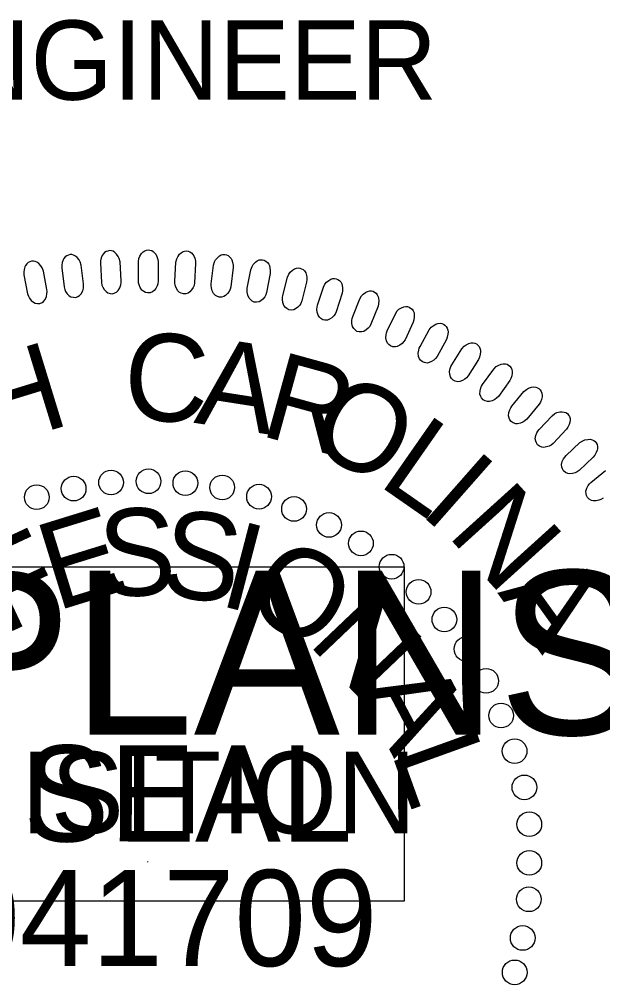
# Model space of a CAD drawing. Extents: x 18938 to 19565, y 6931 to 7973.
# Drawn here: x 19372.4 to 19377.32, y 7796.8 to 7804.94 of the extents above; entities that cross this region are included whole.
import ezdxf

# ---------------------------------------------------------------- set-up
doc = ezdxf.new("R2010")
doc.units = 0
for name, color, linetype in [('Old_Level_10', 7, 'Continuous'), ('Prop Pavement Schedule Description CELL', 7, 'Continuous'), ('Scratch_Level_5', 7, 'Continuous'), ('Typical Pavement Slope Information CELL', 7, 'Continuous')]:
    doc.layers.add(name, color=color, linetype=linetype)

# ---------------------------------------------------------------- blocks, each defined once
blk = doc.blocks.new('Gregory K. Goins')
at = {"layer": 'Old_Level_10'}
blk.add_line((-51.239, 50.97), (-51.239, 50.923), dxfattribs=at)
for points in [[(-55.384, 88.444), (-55.538, 89.661), (-55.602, 89.875), (-55.672, 90.006), (-55.804, 90.161), (-55.914, 90.257), (-56.035, 90.322), (-56.145, 90.349), (-56.258, 90.355), (-56.367, 90.321), (-56.482, 90.276), (-56.578, 90.204), (-56.67, 90.092), (-56.719, 90.005), (-56.767, 89.848), (-56.804, 89.663), (-56.806, 89.502), (-56.656, 88.254), (-56.613, 88.088), (-56.551, 87.955), (-56.442, 87.808), (-56.313, 87.684), (-56.207, 87.617), (-56.044, 87.577), (-55.893, 87.576), (-55.75, 87.634), (-55.652, 87.697), (-55.538, 87.812), (-55.441, 87.995), (-55.397, 88.181), (-55.384, 88.313)], [(-52.946, 88.647), (-53.023, 89.871), (-53.074, 90.088), (-53.135, 90.223), (-53.257, 90.386), (-53.361, 90.49), (-53.478, 90.562), (-53.585, 90.596), (-53.698, 90.608), (-53.809, 90.581), (-53.926, 90.544), (-54.027, 90.478), (-54.125, 90.372), (-54.18, 90.288), (-54.238, 90.135), (-54.286, 89.952), (-54.298, 89.792), (-54.227, 88.537), (-54.195, 88.369), (-54.141, 88.232), (-54.042, 88.079), (-53.921, 87.947), (-53.819, 87.873), (-53.658, 87.823), (-53.508, 87.812), (-53.361, 87.862), (-53.26, 87.918), (-53.139, 88.026), (-53.031, 88.202), (-52.975, 88.386), (-52.953, 88.517)], [(-51.831, 88.656), (-51.831, 89.882), (-51.793, 90.102), (-51.74, 90.242), (-51.628, 90.411), (-51.531, 90.521), (-51.419, 90.601), (-51.315, 90.64), (-51.202, 90.66), (-51.09, 90.64), (-50.97, 90.61), (-50.866, 90.551), (-50.761, 90.451), (-50.701, 90.37), (-50.634, 90.221), (-50.574, 90.042), (-50.552, 89.882), (-50.545, 88.626), (-50.567, 88.456), (-50.613, 88.316), (-50.702, 88.157), (-50.815, 88.017), (-50.912, 87.938), (-51.069, 87.878), (-51.218, 87.858), (-51.367, 87.898), (-51.472, 87.947), (-51.6, 88.047), (-51.719, 88.217), (-51.786, 88.397), (-51.816, 88.526)], [(-49.472, 88.629), (-49.394, 89.854), (-49.344, 90.07), (-49.282, 90.206), (-49.159, 90.368), (-49.056, 90.472), (-48.939, 90.544), (-48.832, 90.577), (-48.718, 90.59), (-48.608, 90.563), (-48.49, 90.526), (-48.39, 90.46), (-48.291, 90.354), (-48.237, 90.27), (-48.179, 90.117), (-48.131, 89.934), (-48.118, 89.773), (-48.191, 88.518), (-48.223, 88.35), (-48.277, 88.214), (-48.377, 88.061), (-48.497, 87.928), (-48.599, 87.854), (-48.76, 87.805), (-48.911, 87.794), (-49.057, 87.843), (-49.158, 87.9), (-49.279, 88.008), (-49.387, 88.184), (-49.443, 88.368), (-49.465, 88.499)], [(-47.109, 88.454), (-46.955, 89.671), (-46.891, 89.884), (-46.821, 90.016), (-46.689, 90.17), (-46.578, 90.267), (-46.457, 90.332), (-46.348, 90.359), (-46.235, 90.364), (-46.126, 90.33), (-46.011, 90.285), (-45.915, 90.213), (-45.823, 90.101), (-45.774, 90.014), (-45.726, 89.857), (-45.69, 89.671), (-45.687, 89.511), (-45.838, 88.263), (-45.881, 88.097), (-45.943, 87.965), (-46.052, 87.818), (-46.181, 87.693), (-46.287, 87.626), (-46.451, 87.587), (-46.601, 87.585), (-46.745, 87.644), (-46.842, 87.706), (-46.956, 87.821), (-47.054, 88.005), (-47.097, 88.191), (-47.111, 88.324)], [(-57.766, 88.076), (-57.995, 89.281), (-58.073, 89.489), (-58.15, 89.617), (-58.292, 89.763), (-58.408, 89.852), (-58.533, 89.91), (-58.643, 89.929), (-58.758, 89.928), (-58.864, 89.887), (-58.975, 89.835), (-59.067, 89.757), (-59.152, 89.639), (-59.195, 89.55), (-59.233, 89.39), (-59.258, 89.203), (-59.251, 89.042), (-59.023, 87.806), (-58.969, 87.644), (-58.899, 87.515), (-58.781, 87.375), (-58.645, 87.259), (-58.534, 87.199), (-58.369, 87.169), (-58.219, 87.178), (-58.079, 87.245), (-57.985, 87.314), (-57.879, 87.435), (-57.794, 87.624), (-57.761, 87.813), (-57.756, 87.946)], [(-44.77, 88.168), (-44.54, 89.372), (-44.462, 89.581), (-44.384, 89.708), (-44.242, 89.854), (-44.126, 89.943), (-44.001, 90), (-43.891, 90.02), (-43.777, 90.019), (-43.671, 89.978), (-43.559, 89.926), (-43.467, 89.848), (-43.383, 89.73), (-43.339, 89.641), (-43.301, 89.481), (-43.276, 89.294), (-43.284, 89.132), (-43.513, 87.897), (-43.567, 87.735), (-43.637, 87.606), (-43.755, 87.466), (-43.891, 87.35), (-44.002, 87.29), (-44.167, 87.26), (-44.318, 87.269), (-44.457, 87.336), (-44.55, 87.405), (-44.656, 87.527), (-44.742, 87.716), (-44.775, 87.904), (-44.779, 88.038)], [(-42.465, 87.694), (-42.159, 88.882), (-42.069, 89.085), (-41.983, 89.208), (-41.832, 89.344), (-41.711, 89.426), (-41.582, 89.475), (-41.471, 89.488), (-41.357, 89.479), (-41.254, 89.432), (-41.145, 89.373), (-41.059, 89.289), (-40.983, 89.167), (-40.945, 89.075), (-40.917, 88.913), (-40.903, 88.724), (-40.921, 88.563), (-41.227, 87.345), (-41.291, 87.187), (-41.37, 87.062), (-41.496, 86.93), (-41.639, 86.823), (-41.753, 86.769), (-41.92, 86.751), (-42.07, 86.769), (-42.204, 86.845), (-42.293, 86.919), (-42.392, 87.047), (-42.466, 87.241), (-42.486, 87.432), (-42.483, 87.564)], [(-40.215, 87.072), (-39.835, 88.239), (-39.732, 88.436), (-39.639, 88.552), (-39.48, 88.679), (-39.353, 88.753), (-39.222, 88.794), (-39.11, 88.8), (-38.997, 88.784), (-38.897, 88.73), (-38.793, 88.664), (-38.711, 88.575), (-38.643, 88.449), (-38.611, 88.354), (-38.593, 88.191), (-38.592, 88.002), (-38.619, 87.843), (-39.001, 86.646), (-39.075, 86.491), (-39.161, 86.372), (-39.295, 86.248), (-39.446, 86.151), (-39.562, 86.105), (-39.73, 86.096), (-39.879, 86.124), (-40.008, 86.208), (-40.092, 86.288), (-40.183, 86.422), (-40.244, 86.62), (-40.252, 86.811), (-40.24, 86.944)], [(-37.931, 86.337), (-37.48, 87.477), (-37.364, 87.667), (-37.264, 87.778), (-37.097, 87.895), (-36.966, 87.961), (-36.833, 87.993), (-36.721, 87.992), (-36.609, 87.97), (-36.513, 87.91), (-36.412, 87.838), (-36.337, 87.743), (-36.276, 87.612), (-36.25, 87.516), (-36.242, 87.352), (-36.253, 87.163), (-36.291, 87.007), (-36.747, 85.835), (-36.831, 85.686), (-36.924, 85.573), (-37.066, 85.458), (-37.221, 85.369), (-37.341, 85.331), (-37.509, 85.333), (-37.656, 85.37), (-37.78, 85.462), (-37.859, 85.547), (-37.94, 85.686), (-37.988, 85.888), (-37.985, 86.08), (-37.965, 86.211)], [(-35.69, 85.403), (-35.167, 86.513), (-35.04, 86.695), (-34.933, 86.799), (-34.76, 86.905), (-34.625, 86.963), (-34.49, 86.987), (-34.378, 86.979), (-34.268, 86.949), (-34.175, 86.883), (-34.079, 86.805), (-34.01, 86.706), (-33.958, 86.571), (-33.938, 86.474), (-33.941, 86.309), (-33.963, 86.122), (-34.011, 85.968), (-34.54, 84.828), (-34.632, 84.684), (-34.733, 84.577), (-34.882, 84.471), (-35.043, 84.392), (-35.165, 84.361), (-35.332, 84.374), (-35.476, 84.42), (-35.593, 84.52), (-35.667, 84.609), (-35.74, 84.754), (-35.775, 84.958), (-35.76, 85.149), (-35.732, 85.279)], [(-33.566, 84.388), (-32.975, 85.462), (-32.836, 85.636), (-32.723, 85.734), (-32.543, 85.828), (-32.405, 85.877), (-32.268, 85.893), (-32.158, 85.878), (-32.05, 85.841), (-31.961, 85.77), (-31.871, 85.686), (-31.808, 85.583), (-31.764, 85.445), (-31.75, 85.346), (-31.763, 85.183), (-31.798, 84.997), (-31.854, 84.846), (-32.454, 83.742), (-32.555, 83.604), (-32.662, 83.503), (-32.817, 83.407), (-32.983, 83.338), (-33.107, 83.315), (-33.273, 83.338), (-33.414, 83.393), (-33.526, 83.5), (-33.593, 83.594), (-33.656, 83.743), (-33.679, 83.949), (-33.652, 84.139), (-33.616, 84.267)], [(-31.508, 83.203), (-30.85, 84.238), (-30.701, 84.403), (-30.582, 84.493), (-30.397, 84.576), (-30.256, 84.617), (-30.118, 84.624), (-30.009, 84.602), (-29.903, 84.558), (-29.819, 84.481), (-29.735, 84.392), (-29.678, 84.285), (-29.643, 84.145), (-29.636, 84.046), (-29.659, 83.883), (-29.705, 83.699), (-29.771, 83.553), (-30.439, 82.488), (-30.549, 82.357), (-30.661, 82.264), (-30.823, 82.177), (-30.992, 82.119), (-31.117, 82.103), (-31.282, 82.137), (-31.418, 82.201), (-31.523, 82.314), (-31.585, 82.413), (-31.639, 82.565), (-31.649, 82.772), (-31.609, 82.96), (-31.565, 83.085)], [(-29.508, 81.929), (-28.787, 82.921), (-28.628, 83.078), (-28.503, 83.16), (-28.313, 83.231), (-28.17, 83.262), (-28.032, 83.261), (-27.924, 83.231), (-27.821, 83.182), (-27.742, 83.1), (-27.664, 83.005), (-27.614, 82.896), (-27.588, 82.753), (-27.586, 82.653), (-27.62, 82.493), (-27.677, 82.313), (-27.753, 82.17), (-28.486, 81.149), (-28.604, 81.026), (-28.722, 80.939), (-28.888, 80.862), (-29.061, 80.815), (-29.187, 80.808), (-29.349, 80.852), (-29.481, 80.924), (-29.579, 81.044), (-29.634, 81.146), (-29.679, 81.301), (-29.675, 81.509), (-29.624, 81.694), (-29.572, 81.816)], [(-27.614, 80.513), (-26.831, 81.458), (-26.663, 81.603), (-26.534, 81.678), (-26.339, 81.737), (-26.194, 81.76), (-26.057, 81.749), (-25.951, 81.713), (-25.852, 81.657), (-25.778, 81.571), (-25.705, 81.471), (-25.663, 81.358), (-25.646, 81.215), (-25.65, 81.115), (-25.695, 80.957), (-25.762, 80.78), (-25.846, 80.643), (-26.642, 79.671), (-26.768, 79.554), (-26.892, 79.475), (-27.062, 79.41), (-27.238, 79.373), (-27.364, 79.373), (-27.523, 79.428), (-27.65, 79.508), (-27.74, 79.634), (-27.789, 79.739), (-27.823, 79.897), (-27.807, 80.103), (-27.744, 80.285), (-27.684, 80.404)], [(-25.842, 78.999), (-25.002, 79.893), (-24.825, 80.028), (-24.691, 80.094), (-24.493, 80.14), (-24.347, 80.154), (-24.211, 80.135), (-24.107, 80.093), (-24.011, 80.03), (-23.944, 79.939), (-23.877, 79.835), (-23.841, 79.72), (-23.834, 79.576), (-23.845, 79.476), (-23.898, 79.321), (-23.977, 79.15), (-24.07, 79.018), (-24.926, 78.097), (-25.058, 77.989), (-25.186, 77.918), (-25.361, 77.864), (-25.538, 77.838), (-25.664, 77.847), (-25.819, 77.91), (-25.942, 77.998), (-26.023, 78.13), (-26.065, 78.238), (-26.09, 78.397), (-26.061, 78.603), (-25.987, 78.779), (-25.92, 78.894)], [(-24.098, 77.306), (-23.203, 78.145), (-23.018, 78.268), (-22.88, 78.326), (-22.68, 78.36), (-22.533, 78.364), (-22.399, 78.337), (-22.297, 78.288), (-22.206, 78.22), (-22.144, 78.124), (-22.084, 78.017), (-22.056, 77.899), (-22.057, 77.755), (-22.075, 77.657), (-22.138, 77.505), (-22.227, 77.339), (-22.328, 77.213), (-23.24, 76.348), (-23.379, 76.248), (-23.511, 76.185), (-23.689, 76.142), (-23.867, 76.128), (-23.992, 76.144), (-24.143, 76.218), (-24.26, 76.313), (-24.334, 76.449), (-24.369, 76.56), (-24.383, 76.721), (-24.341, 76.924), (-24.256, 77.096), (-24.182, 77.206)]]:
    blk.add_lwpolyline(points, close=True, dxfattribs=at)
blk.add_lwpolyline([(-21.69, 74.55), (-21.834, 74.459), (-21.971, 74.404), (-22.151, 74.372), (-22.33, 74.369), (-22.453, 74.393), (-22.6, 74.476), (-22.71, 74.579), (-22.774, 74.719), (-22.803, 74.832), (-22.807, 74.993), (-22.752, 75.193), (-22.657, 75.36), (-22.576, 75.465), (-22.486, 75.559), (-21.54, 76.341)], dxfattribs=at)
for centre in [(-51.174, 75.639), (-56.031, 75.163), (-53.603, 75.56), (-48.785, 75.519), (-46.397, 75.239), (-58.42, 74.606), (-44.008, 74.641), (-41.739, 73.843), (-39.47, 72.807), (-37.4, 71.611), (-35.41, 70.097), (-33.659, 68.463), (-31.987, 66.669), (-30.554, 64.757), (-29.281, 62.685), (-28.309, 60.436), (-27.434, 58.125), (-26.797, 55.774), (-26.48, 53.384), (-26.48, 50.874), (-26.51, 48.51), (-26.909, 46.001), (-27.427, 43.77)]:
    blk.add_circle(centre, 0.801, dxfattribs=at)
for s, height, rotation, p in [('C', 5.669, 357.58768, (-52.856, 79.65)), ('H', 5.669, 17.05575, (-61.361, 77.767)), ('A', 5.669, 351.09832, (-48.281, 79.442)), ('R', 5.669, 344.60896, (-44.074, 78.648)), ('O', 5.669, 331.63025, (-41.119, 77.994)), ('L', 5.669, 325.14089, (-36.386, 75.463)), ('I', 5.669, 318.65154, (-33.693, 73.61)), ('N', 5.669, 312.16218, (-31.888, 72.189)), ('E', 5.669, 17.16862, (-57.165, 67.198)), ('S', 5.669, 1.28903, (-54.398, 68.157)), ('S', 5.669, 353.34923, (-50.537, 68.259)), ('I', 5.669, 345.40944, (-46.736, 67.627)), ('F', 5.669, 25.10842, (-60.555, 65.659)), ('O', 5.669, 329.52984, (-45.233, 67.455)), ('A', 5.669, 305.67282, (-28.568, 68.409)), ('N', 5.669, 313.65025, (-40.921, 65.151)), ('A', 5.669, 297.77065, (-37.584, 62.07)), ('L', 5.669, 289.83086, (-35.46, 58.076)), ('SEAL', 6.2363, 359.98136, (-59.282, 52.264)), ('041709', 6.2363, 359.98136, (-64.157, 44.186))]:
    blk.add_text(s, height=height, rotation=rotation, dxfattribs=at).set_placement(p)

msp = doc.modelspace()

# ---------------------------------------------------------------- linework, layer by layer
at = {"layer": 'Scratch_Level_5'}
msp.add_lwpolyline([(19358.0043, 7797.5026), (19358.0043, 7800.3226), (19375.6443, 7800.3226), (19375.6443, 7797.5026)], close=True, dxfattribs=at)

# ---------------------------------------------------------------- block references
at = {"layer": 'Prop Pavement Schedule Description CELL', "xscale": 0.13, "yscale": 0.13}
msp.add_blockref('Gregory K. Goins', (19380.142, 7791.211), dxfattribs=at)

# ---------------------------------------------------------------- texts
at = {"layer": 'Scratch_Level_5'}
for s, height, p in [('INCOMPLETE PLANS', 1.3824, (19359.0783, 7798.9066)), ('DO NOT USE FOR R/W ACQUISITION', 0.6912, (19359.4683, 7798.0726))]:
    msp.add_text(s, height=height, dxfattribs=at).set_placement(p)
at = {"layer": 'Typical Pavement Slope Information CELL'}
msp.add_text('ENGINEER', height=0.66866, dxfattribs=at).set_placement((19371.2523, 7804.263))

doc.saveas('drawing.dxf')
